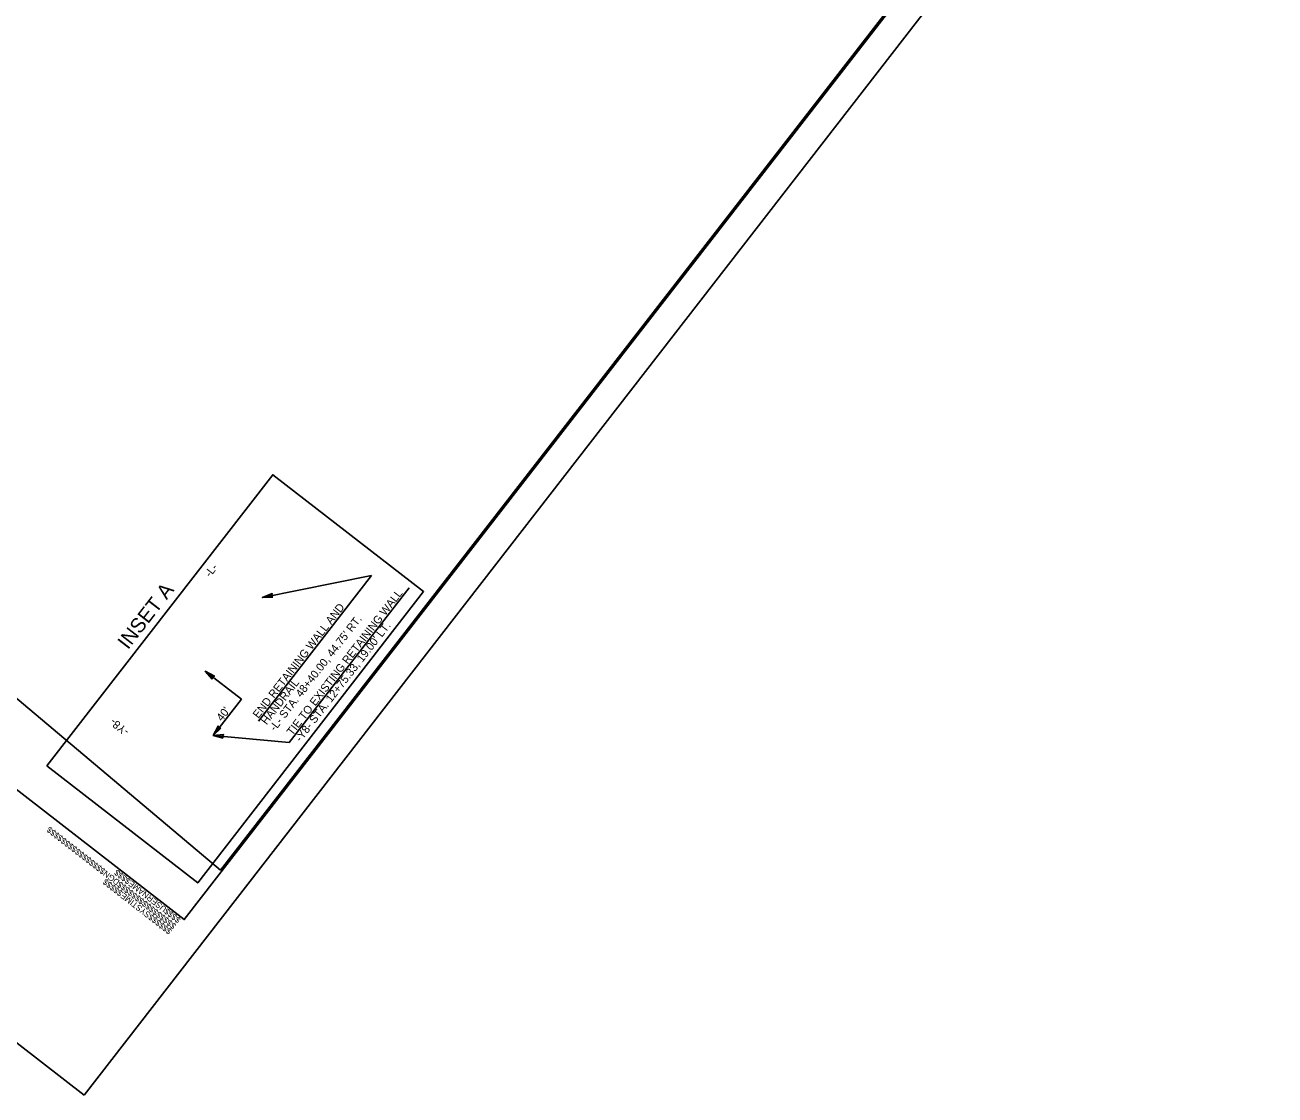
# Model space of a CAD drawing. Extents: x 2013373 to 2015284, y 444589 to 446636.
# Drawn here: x 2014190 to 2015284, y 444618 to 445554 of the extents above; entities that cross this region are included whole.
import ezdxf

# ---------------------------------------------------------------- set-up
doc = ezdxf.new("R2010")
doc.units = 0
for name, color, linetype in [('Prop Dimension', 7, 'Continuous'), ('Prop Dimension Text', 7, 'Continuous'), ('Prop Horizontal Alignment Tick Label', 7, 'Continuous'), ('Prop Terminator CELL', 7, 'Continuous'), ('Sheet Block System Information CELL', 7, 'Continuous'), ('Sheet Clip Boundary CELL', 7, 'Continuous'), ('Sheet Plan And Profile CELL', 7, 'Continuous'), ('Sheet Plot Border Outside CELL', 7, 'Continuous')]:
    doc.layers.add(name, color=color, linetype=linetype)

msp = doc.modelspace()

# ---------------------------------------------------------------- linework, layer by layer
at = {"layer": 'Prop Dimension'}
for p, q in [((2014394.5, 444945.2), (2014493.3, 445072.7)), ((2014397.9, 445053.5), (2014493.3, 445072.7)), ((2014421.1, 444926.4), (2014526.1, 445061.8)), ((2014347.8, 444988.9), (2014379.4, 444964.4)), ((2014354.8, 444932.8), (2014379.4, 444964.4)), ((2014421.1, 444926.4), (2014354.8, 444932.8))]:
    msp.add_line(p, q, dxfattribs=at)
at = {"layer": 'Prop Terminator CELL'}
for points in [[(2014407, 445053.7), (2014397.9, 445053.5), (2014406.4, 445056.8), (2014405.6, 445055)], [(2014353.9, 444982.1), (2014347.8, 444988.9), (2014355.9, 444984.6), (2014354, 444984)], [(2014361.5, 444939), (2014354.8, 444932.8), (2014359.1, 444940.9), (2014359.6, 444939.1)], [(2014363.6, 444930.4), (2014354.8, 444932.8), (2014363.9, 444933.5), (2014362.6, 444932.1)]]:
    msp.add_lwpolyline(points, close=True, dxfattribs=at)
at = {"layer": 'Sheet Block System Information CELL'}
msp.add_line((2014329.4, 444771.6), (2014329.4, 444771.6), dxfattribs=at)
at = {"layer": 'Sheet Clip Boundary CELL'}
msp.add_lwpolyline([(2014175.9, 446280.2), (2013513.1, 445427.6), (2013603.8, 445375.4), (2013612.4, 445329.9), (2013915.8, 445258.4), (2014042, 445083.4), (2014361.1, 444814.9), (2015247.4, 445957.7), (2014564.2, 446487.4), (2014441.6, 446328.9), (2014350.6, 446399.7), (2014226.8, 446240.6)], close=True, dxfattribs=at)
at = {"layer": 'Sheet Plan And Profile CELL'}
msp.add_line((2014329.4, 444771.6), (2014329.4, 444771.6), dxfattribs=at)
msp.add_line((2014329.4, 444771.6), (2014329.4, 444771.6), dxfattribs=at)
for points in [[(2014418.9, 446600.4), (2013499.7, 445415.1), (2014329.4, 444771.6), (2015248.7, 445957)], [(2014209.2, 444906.1), (2014406.9, 445160.9), (2014538.8, 445058.6), (2014341.2, 444803.7)]]:
    msp.add_lwpolyline(points, close=True, dxfattribs=at)
at = {"layer": 'Sheet Plot Border Outside CELL'}
msp.add_lwpolyline([(2014241.9, 444618), (2015283.7, 445961.4), (2014414.5, 446635.5), (2013372.7, 445292.2)], close=True, dxfattribs=at)

# ---------------------------------------------------------------- texts
at = {"layer": 'Prop Dimension Text'}
for s, height, rotation, p in [('INSET A', 12.83, 52.2051, (2014280.2, 445007.2)), ('TIE TO EXISTING RETAINING WALL', 7, 52.2051, (2014424, 444932.1)), ('END RETAINING WALL AND', 7, 52.2051, (2014394.3, 444947.1)), ("-L- STA. 48+40.00, 44.75' RT. ", 7, 52.2051, (2014408.8, 444935.9)), ("-Y8- STA. 12+75.33, 19.00' LT. ", 7, 52.2051, (2014431.2, 444926.5)), ('HANDRAIL', 7, 52.2051, (2014401.5, 444941.5)), ("40'", 7, 51.9377, (2014362.4, 444944.6))]:
    msp.add_text(s, height=height, rotation=rotation, dxfattribs=at).set_placement(p)
at = {"layer": 'Prop Horizontal Alignment Tick Label'}
for s, rotation, p in [('-L-', 52.2051, (2014352.1, 445070.6)), ('-Y8-', 142.1122, (2014281.8, 444937.4))]:
    msp.add_text(s, height=7, rotation=rotation, dxfattribs=at).set_placement(p)
at = {"layer": 'Sheet Block System Information CELL'}
for s, p in [('$$$$$$$$$$$$$$$$DGN$$$$$$$$$$$$$$$$', (2014322.8, 444767)), ('$$$$USERNAME$$$$', (2014326.9, 444772.2)), ('$$$$$$SYSTIME$$$$$', (2014319.1, 444762.3))]:
    msp.add_text(s, height=5.25, rotation=142.2051, dxfattribs=at).set_placement(p)

doc.saveas('drawing.dxf')
